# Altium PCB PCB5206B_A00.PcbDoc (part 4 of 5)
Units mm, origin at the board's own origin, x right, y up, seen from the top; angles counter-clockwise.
Board outline 115 x 60 mm, 6 copper layers (Top Layer, GND Layer 2, Signal Layer 3, Signal Layer 4, VCC Layer 5, Bottom Layer), stack 1.555 mm thick; 384 components, 267 nets, 1313 pads, 834 vias.
Unrouted connection lines stored in the file: 10.
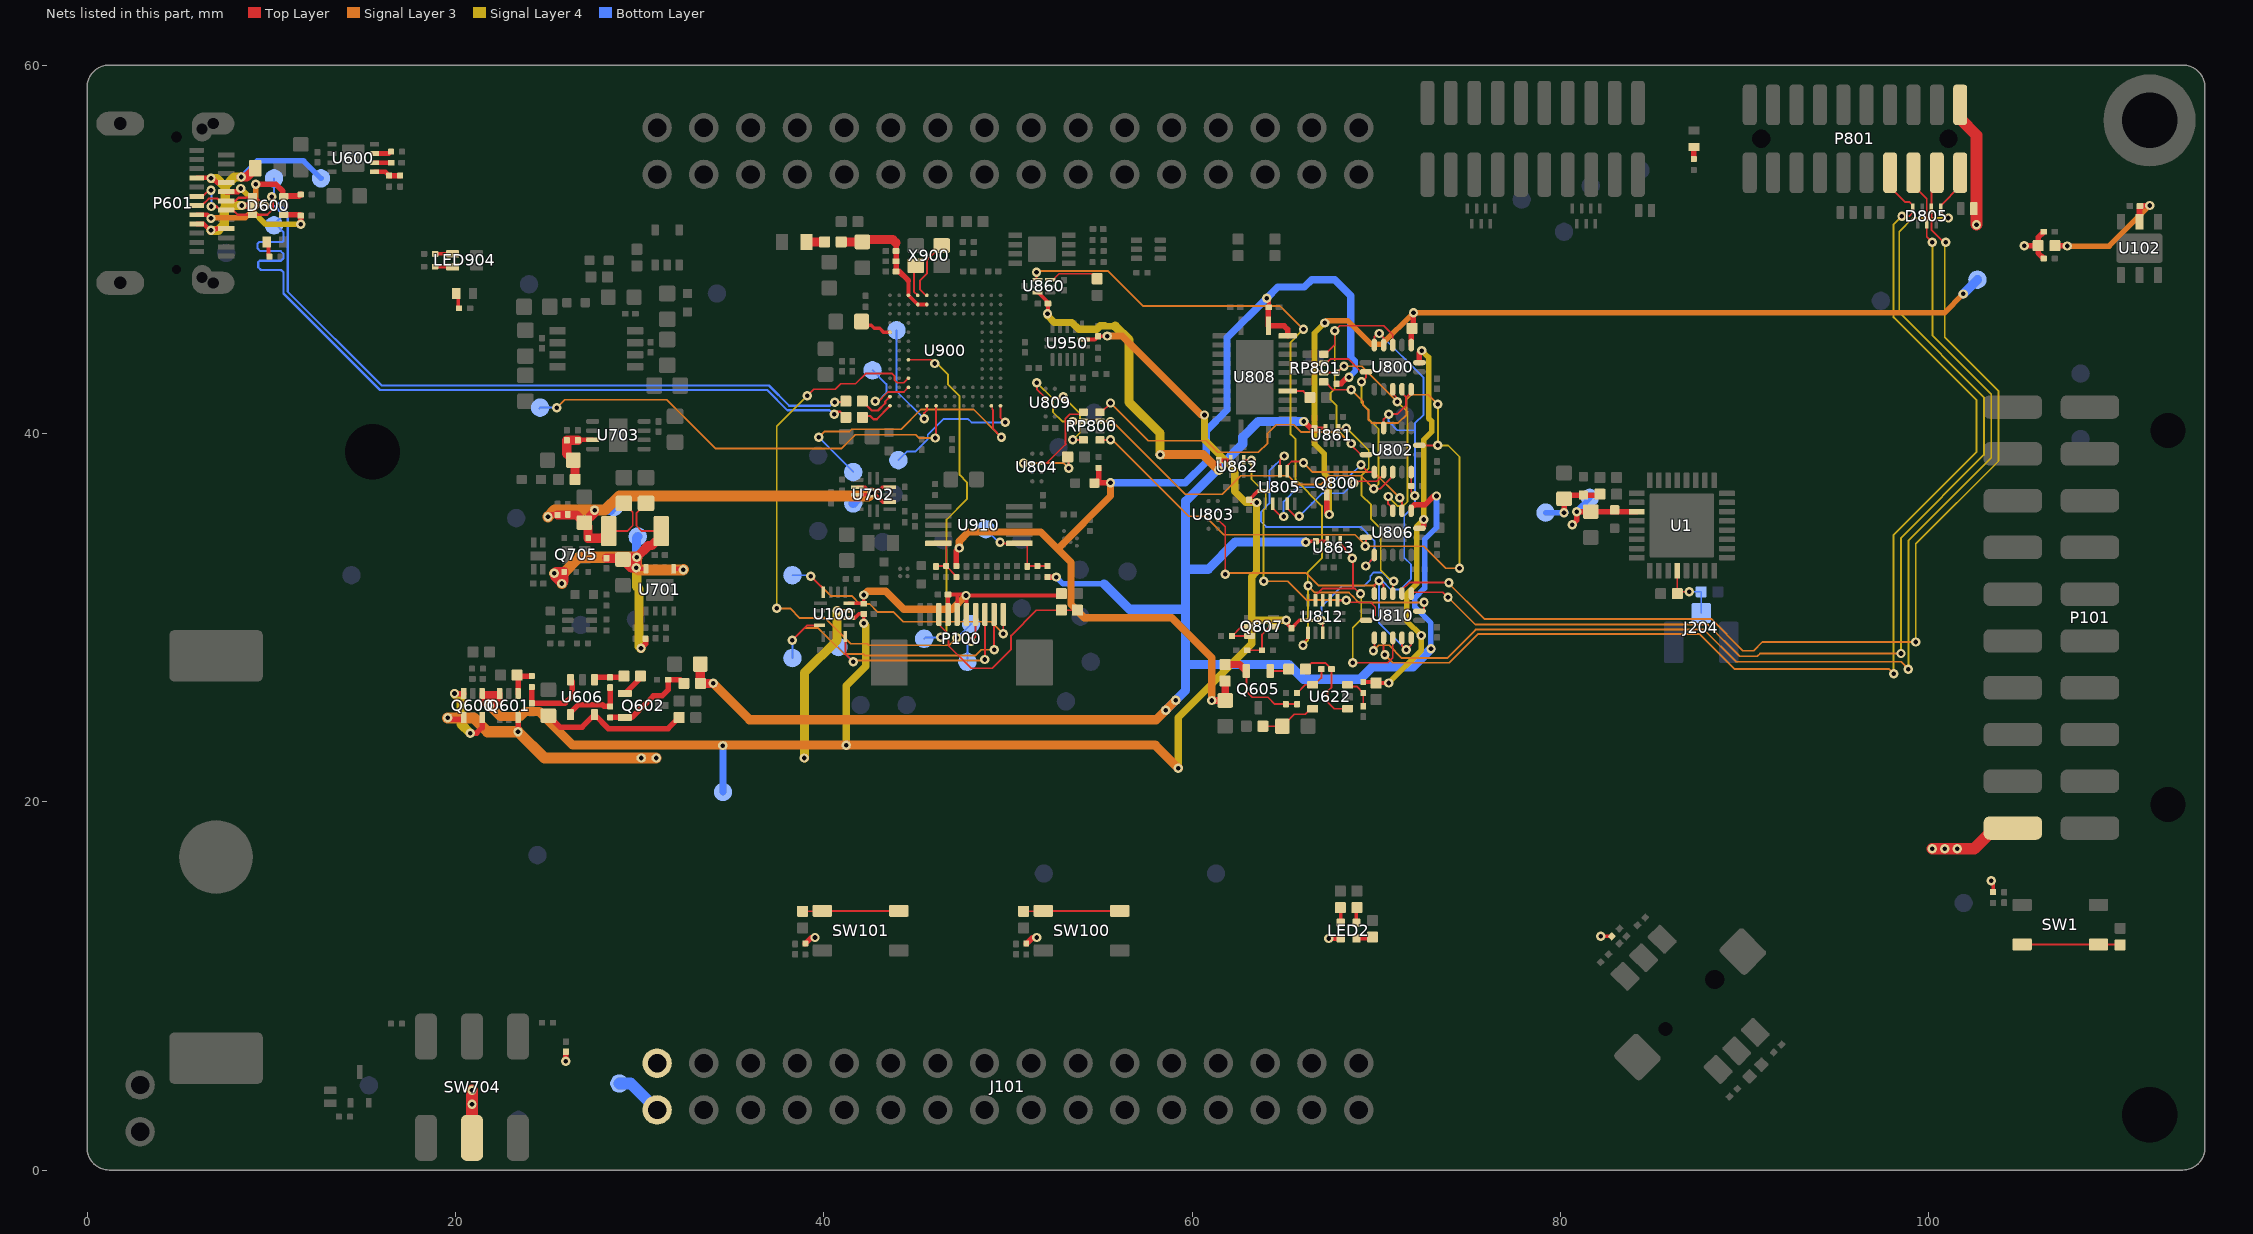
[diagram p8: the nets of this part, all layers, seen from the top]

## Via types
v1: diameter 0.508, hole 0.25, Top Layer to Bottom Layer, tented both sides, 834 vias

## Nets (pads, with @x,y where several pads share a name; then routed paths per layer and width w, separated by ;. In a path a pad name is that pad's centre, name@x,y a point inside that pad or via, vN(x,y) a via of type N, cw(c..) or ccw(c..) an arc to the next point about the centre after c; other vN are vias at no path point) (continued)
N16846723: R805.1 U808.17 | length 1.3
  Top Layer w0.1: U808.17@65.195,42.3 66.05,42.3 R805.1@66.4,41.95
N16846896: RP800.8 U809.C1 | length 3.9
  Top Layer w0.1: U809.C1@52.55,41.925 v1@52.975,41.925 ; v1(53.525,39.65) RP800.8@54.1,39.65
  Signal Layer 4 w0.1: v1(53,42) 53.925,41.075 53.925,40.05 v1(53.525,39.65)
N16846900: RP800.6 U809.C2 | length 4.8
  Top Layer w0.1: v1(51.575,42.75) 51.575,42.4 U809.C2@52.05,41.925 ; v1(53.525,40.65) RP800.6@54.1,40.65
  Signal Layer 4 w0.1: v1(51.575,42.75) 52.45,41.875 52.45,41.15 52.95,40.65 v1(53.525,40.65)
N16846924: RP800.5 U804.C1 | length 4.2
  Top Layer w0.1: U804.C1@51.825,38.4 52.125,38.4 53.125,39.4 53.125,40.8 53.132,40.807 53.132,40.813 53.362,41.043 53.993,41.043 RP800.5@54.1,41.15
N16847739: U805.10 U806.9 | length 13.9
  Top Layer w0.1: U805.10@64.775,37.955 64.775,38.55 v1(65,38.775) ; v1(69.425,32.8) 69.9,33.275 U806.9@69.9,33.4
  Bottom Layer w0.1: v1(65,38.775) 64.2,37.975 64.2,36.2 63.75,35.75 63.75,35.2 64.025,34.925 69.15,34.925 69.9,34.175 69.9,33.275 v1(69.425,32.8)
N16847741: U805.9 U806.3 | length 8.1
  Top Layer w0.1: U805.9@65.175,37.955 65.175,38.25 65.4,38.475 65.975,38.475 v1(66.05,38.4) ; v1(71.275,36.5) 71.4,36.375 U806.3@71.4,35.8
  Signal Layer 3 w0.1: v1(66.05,38.4) 66.55,37.9 69.881,37.9 71.275,36.506 v1(71.275,36.5)
N16847743: U802.10 U805.4 | length 6.7
  Top Layer w0.1: U805.4@65.175,36.185 65.175,35.925 65.6,35.5 v1(65.825,35.5) ; v1(68.775,37.3) 68.875,37.4 69.776,37.4 70.024,37.4 70.4,37.776 U802.10@70.4,37.9
  Bottom Layer w0.1: v1(65.825,35.5) 67.075,36.75 68.225,36.75 v1(68.775,37.3)
N16847749: U802.9 U805.2 | length 7.7
  Top Layer w0.1: U805.2@64.375,36.185 64.375,35.945 v1@64.795,35.525 ; v1@69,38.3 v1(69.175,38.3) 69.575,37.9 U802.9@69.9,37.9
  Bottom Layer w0.1: v1(64.975,35.491) 64.975,36.3 65.75,37.075 67.375,37.075 68,37.7 68.575,37.7 v1(69.175,38.3)
N16847975: R810.1 U804.C2 | length 3.7
  Top Layer w0.1: v1(50.85,38.388) 50.863,38.4 U804.C2@51.325,38.4 ; R810.1@53.25,38.725 53.3,38.675 v1(53.3,38.1)
  Signal Layer 3 w0.1: v1(50.85,38.388) 53.038,38.388 53.325,38.1 v1(53.3,38.1)
N16916520: U810.1 U812.1 U860.4 | length 43
  Top Layer w0.1: v1(51.553,48.752) 51.553,48.397 U860.4@51.6,48.35 ; v1(66.025,28.5) 66.025,28.625 66.3,28.9 U812.1@66.3,29.165 ; U810.1@72.35,30.35 72.375,30.375 72.55,30.375 72.6,30.425 v1(72.6,30.825)
  Signal Layer 3 w0.1: v1(51.553,48.752) 51.625,48.825 55.425,48.825 57.325,46.925 64.775,46.925 v1(66.05,45.65) ; v1(66.3,31.725) 66.668,31.357 68.524,31.357 68.807,31.074 68.807,31.062 69.037,30.832 69.049,30.832 69.056,30.825 v1(72.6,30.825)
  Signal Layer 4 w0.1: v1(66.025,28.5) 66.3,28.775 v1(66.3,31.725) 66.287,31.738 66.287,32.462 67.05,33.225 67.05,36.05 65.625,37.475 65.625,39.675 65.35,39.95 65.35,44.95 v1(66.05,45.65)
N16916530: U810.4 U812.3 U861.4 | length 17.4
  Top Layer w0.1: v1(67.025,29.85) 67.1,29.775 U812.3@67.1,29.165 ; U861.4@67.95,40.25 68.425,40.25 v1@68.45,40.275 ; U810.4@70.9,31.3 70.9,31.875 70.95,31.925 v1(70.95,31.975)
  Signal Layer 4 w0.1: v1(68.375,40.275) 68.4,40.275 69.6,39.075 69.6,38.1 69.2,37.7 69.2,36.65 69.725,36.125 69.725,35.35 70.25,34.825 70.25,32.575 70.85,31.975 v1(70.95,31.975)
  Bottom Layer w0.1: v1(67.025,29.85) 67.025,30.6 68.15,31.725 69.35,31.725 69.675,32.05 69.675,32.25 69.875,32.45 70.325,32.45 70.8,31.975 v1(70.95,31.975)
N16916558: U810.11 U812.11 U863.4 | length 13.2
  Top Layer w0.1: U812.11@66.7,30.935 66.7,31.2 67.075,31.575 68.743,31.575 ; U863.4@68.05,34.15 68.05,34.025 68.3,33.775 68.3,33.7 68.7,33.3 v1(68.7,33.225) 68.743,33.182 68.743,31.575 ; v1@68.723,27.55 70.625,27.55 70.9,27.825 U810.11@70.9,28.9 ; v1(69.15,31.3) 69.125,31.3 68.85,31.575 68.743,31.575
  Signal Layer 4 w0.1: v1(68.725,27.55) 68.725,29.439 69.193,29.907 69.193,31.218 69.15,31.261 v1(69.15,31.3)
N16916616: U810.8 U812.8 U862.4 | length 15.5
  Top Layer w0.1: U862.4@62.8,38.55 v1(63.225,38.55) ; U812.8@67.9,30.935 68.36,30.935 v1(68.375,30.95) 68.493,30.832 69.693,30.832 69.95,30.575 69.95,30.125 69.675,29.85 U810.8@69.45,29.85
  Signal Layer 3 w0.1: v1(63.9,31.975) 65.2,31.975 66.225,30.95 v1(68.375,30.95)
  Signal Layer 4 w0.1: v1(63.225,38.55) 63.225,37.525 64,36.75 64,35.95 63.875,35.825 v1@63.875,31.975
N16917071: R882.1 U860.3 | length 2.8
  Top Layer w0.1: U860.3@52.3,48.35 52.45,48.35 52.775,48.675 54.575,48.675 R882.1@54.85,48.4
N16922979: R601.1 R602.2 U600.5 | length 1.5
  Top Layer w0.25: U600.5@15.6,54.2 16.2,54.2 R601.1@16.4,54
  Top Layer w0.3: R601.1@16.4,54 R602.2@17,54
N16923003: R600.1 U600.7 | length 0.9
  Top Layer w0.25: U600.7@15.6,55.2 16.4,55.2 R600.1@16.5,55.3
N16923019: C602.1 U600.6 | length 0.9
  Top Layer w0.25: U600.6@15.6,54.7 C602.1@16.525,54.7
N16923678: C620.1 R682.2 U606.4 | length 3.5
  Top Layer w0.3: U606.4@26.25,24.725 26.25,24.85 26.675,25.275 27.975,25.275 28.075,25.175 R682.2@28.4,25.175 C620.1@28.4,26.2
N16923728: Q601.4 R628.1 R672.2 | length 1.8
  Top Layer w0.3: R628.1@23.35,26.875 R628.1@23.4,26.825 ; Q601.4@23.4,25.875 R628.1@23.4,26.825 ; R672.2@24.15,26.825 R628.1@23.4,26.825
N16923751: C654.1 R689.2 U622.4 | length 2.1
  Top Layer w0.1: R689.2@65.7,25.9 66.15,26.35 U622.4@66.55,26.35 66.65,26.35 67.025,26.725 C654.1@67.025,27.2
N16923761: Q605.1 R686.2 | length 1
  Top Layer w0.1: Q605.1@64.25,27.1 65.15,27.1 R686.2@65.25,27.2
N16923771: C653.1 R629.1 U622.3 | length 1.8
  Top Layer w0.1: U622.3@68.45,26.35 68.539,26.261 68.939,26.261 R629.1@69.3,25.9 C653.1@69.3,25.175
N16923785: Q605.2 R687.1 R688.1 R689.1 | length 5.4
  Top Layer w0.1: Q605.2@62.95,27.1 62.95,26 63.275,25.675 64.125,25.675 64.5,25.3 R688.1@65.1,25.3 R689.1@65.7,25.3
  Top Layer w0.4: R687.1@61.8,27.45 62.6,27.45 Q605.2@62.95,27.1
N16923803: C654.2 R686.1 U622.1 | length 4.8
  Top Layer w0.1: R686.1@66.15,27.2 66.475,27.525 67.25,27.525 C654.2@67.575,27.2 67.575,26.225 67.35,26 67.35,25.425 67.725,25.05 U622.1@68.45,25.05
N16923899: C652.1 R690.1 U622.5 | length 3.1
  Top Layer w0.1: R690.1@63.85,24.1 C652.1@64.9,24.1 65.55,24.75 66.15,24.75 66.45,25.05 U622.5@66.55,25.05
N16923917: C660.1 R681.1 U606.5 | length 8.2
  Top Layer w0.3: C660.1@25.05,24.675 25.675,24.05 26.875,24.05 U606.5@27.55,24.725 28.3,23.975 31.55,23.975 R681.1@32.15,24.575
N16923949: Q602.1 R679.2 | length 1.3
  Top Layer w0.3: Q602.1@29.2,25.875 30.05,26.725 R679.2@30.05,26.825
N16923963: C621.1 R672.1 U606.3 | length 4.2
  Top Layer w0.3: R672.1@24.15,26.225 C621.1@24.15,25.35 25.95,25.35 26.35,25.75 26.35,26.525 U606.3@26.25,26.625
N16923985: Q602.2 R674.1 R675.1 R682.1 | length 5.3
  Top Layer w0.3: R682.1@28.4,24.575 Q602.2@29.2,24.575 29.575,24.575 30.75,25.75 31.225,25.75 31.55,26.075 R674.1@31.55,26.625 32.2,26.625 R675.1@32.4,26.425
N16924018: C620.2 R679.1 U606.1 | length 1.7
  Top Layer w0.3: U606.1@27.55,26.625 27.675,26.75 C620.2@28.4,26.75 29.075,26.75 R679.1@29.15,26.825
N16924927: Q600.3 Q600.6 | length 4.3
  Top Layer w0.3: v1(19.95,25.875) Q600.6@20.45,25.875 ; v1(20.8,23.725) 21.15,23.725 21.45,24.025 Q600.3@21.45,24.575
  Signal Layer 4 w0.5: v1(19.95,25.875) 20.3,25.525 20.3,24.225 v1(20.8,23.725)
N16934878: C900.1 U900.J13 | length 1.7
  Top Layer w0.2: C900.1@42.05,45.975 42.15,45.875 42.575,45.875 42.743,45.707 43.039,45.707 43.246,45.5 U900.J13@43.6,45.5
N16934900: C903.1 C904.1 C905.1 C906.1 R130.2 U900.M9 U900.M10 U900.N11 | length 7.5
  Top Layer w0.2: 44.6,48.3 U900.N11@44.6,47.5 U900.M10@45.1,47 U900.M9@45.6,47
  Top Layer w0.3: 43.925,50.35 C906.1@43.925,49.9 C905.1@43.925,49.35 C904.1@43.925,48.8 44.1,48.8 44.6,48.3
  Top Layer w0.5: R130.2@40.95,50.4 C903.1@42.1,50.4 42.225,50.525 43.75,50.525 43.925,50.35
N16936696: U900.N10 X900.1 | length 1.7
  Top Layer w0.1: X900.1@45,49.1 44.9,49 44.9,47.7 U900.N10@45.1,47.5
N16936699: U900.N9 X900.3 | length 3.4
  Top Layer w0.1: U900.N9@45.6,47.5 45.55,47.5 45.225,47.825 45.225,48.3 45.6,48.675 45.6,49.4 X900.3@46.4,50.2
N16939106: TPJ909.1 U900.C11 | length 4.5
  Top Layer w0.1: v1(42.8,41.75) 42.873,41.677 42.902,41.677 43.475,42.25 44.35,42.25 U900.C11@44.6,42.5
  Bottom Layer w0.1: TPJ909.1@42.651,43.427 43.4,42.679 43.4,42.2 42.95,41.75 v1(42.8,41.75) v1@42.8,41.7
N16939109: TPJ910.1 U900.D11 | length 30.5
  Top Layer w0.1: v1(39.1,42.05) 39.45,42.4 40.625,42.4 40.925,42.7 41.725,42.7 42.275,43.25 43.714,43.25 43.85,43.114 43.85,42.886 43.986,42.75 44.35,42.75 U900.D11@44.6,43
  Signal Layer 3 w0.1: v1(37.45,30.5) 38.175,30.5 38.7,29.975 40.075,29.975 41.475,28.575 42.375,28.575 42.45,28.5 46.825,28.5 v1(47.225,28.9)
  Signal Layer 4 w0.1: v1(37.45,30.5) 37.45,40.4 v1(39.1,42.05)
  Bottom Layer w0.1: v1(47.225,28.9) 47.253,28.9 TPJ910.1@48.003,29.65
N16939489: TPJ911.1 U900.F11 | length 18.7
  Top Layer w0.1: U900.F11@44.6,44 45.825,44 v1(46.025,43.8)
  Signal Layer 4 w0.1: v1(46.025,43.8) 46.125,43.8 46.75,43.175 46.75,42.65 47.375,42.025 47.375,37.75 47.775,37.35 47.775,36.425 46.675,35.325 46.675,29.25 v1(46.35,28.925)
  Bottom Layer w0.1: TPJ911.1@45.453,28.85 45.528,28.925 v1(46.35,28.925)
N16939638: TPJ900.1 U900.A2 | length 15.8
  Top Layer w0.1: U900.A2@49.1,41.5 49.15,41.45 49.15,41.314 49.2,41.264 49.2,40.25 v1(49.65,39.8)
  Signal Layer 3 w0.1: v1(39.725,39.8) 40.025,40.1 41.4,40.1 41.525,40.225 44.2,40.225 45.275,41.3 48.15,41.3 v1(49.65,39.8)
  Bottom Layer w0.1: v1(39.725,39.8) 41.602,37.923 TPJ900.1@41.602,37.9
N16939640: TPJ901.1 U900.A1 | length 7.9
  Top Layer w0.1: U900.A1@49.6,41.5 49.6,40.85 v1(49.85,40.6)
  Bottom Layer w0.1: TPJ901.1@44.053,38.55 44.528,39.025 45,39.025 45.65,39.675 45.65,39.925 46.5,40.775 47.85,40.775 48.025,40.6 v1(49.85,40.6)
N16940103: TPJ908.1 U900.A9 | length 6.2
  Top Layer w0.1: v1(45.45,40.8) 45.45,41.1 45.6,41.25 U900.A9@45.6,41.5
  Bottom Layer w0.1: TPJ908.1@43.952,45.601 43.952,42.298 v1(45.45,40.8)
N16942491: R902.2 U900.B13 | length 2.1
  Top Layer w0.12: R902.2@42.1,41.75 42.6,41.25 42.95,41.25 43.34,41.64 43.34,41.74 U900.B13@43.6,42
N16942503: R904.2 U900.A13 | length 1.9
  Top Layer w0.12: R904.2@42.1,40.875 42.175,40.95 42.525,40.95 42.7,40.775 42.875,40.775 U900.A13@43.6,41.5
N16943456: TPJ902.1 U900.A8 | length 24.9
  Top Layer w0.1: v1(46.05,39.75) 46.1,39.8 U900.A8@46.1,41.5
  Signal Layer 3 w0.1: v1(25.5,41.4) 25.925,41.825 31.484,41.825 34.134,39.175 40.95,39.175 41.7,39.925 45,39.925 45.175,39.75 v1(46.05,39.75)
  Bottom Layer w0.1: TPJ902.1@24.551,41.351 TPJ902.1@24.6,41.4 v1(25.5,41.4)
N16944010: LED903.2 R912.2 | length 0.9
  Top Layer w0.2: LED903.2@20.05,47.6 20.15,47.5 20.15,46.85 R912.2@20.2,46.8
N16966205: LED904.2 R920.2 | length 0.9
  Top Layer w0.2: R920.2@18.9,49.75 LED904.2@19.85,49.75
N16966207: LED904.1 R919.2 | length 0.9
  Top Layer w0.2: R919.2@18.9,49.05 LED904.1@19.85,49.05
N16966211: LED901.1 R903.2 | length 0.9
  Top Layer w0.2: LED901.1@9.75,50.4 9.85,50.3 9.85,49.65 R903.2@9.9,49.6
N16966215: LED900.1 R900.2 | length 0.7
  Top Layer w0.3: R900.2@87.25,54.9 LED900.1@87.25,55.55
N16996446: Q807.5 Q807.6 R838.1 | length 2.1
  Top Layer w0.1: Q807.6@63.125,29 R838.1@62.175,29 62.675,29.5 Q807.5@63.125,29.5
N16997087: Q807.2 R839.2 R841.2 | length 2.5
  Top Layer w0.1: R841.2@63,28.225 R839.2@63.8,28.225 63.8,29.075 64.225,29.5 Q807.2@64.425,29.5
N17012885: L900.2 R130.1 | length 1
  Top Layer w0.5: L900.2@39.065,50.4 R130.1@40.05,50.4
N17207915: LED2.4 R135.1 | length 0.9
  Top Layer w0.2: LED2.4@68.925,12.575 69.725,12.575 R135.1@69.8,12.65
N17207930: LED2.3 R136.1 | length 0.9
  Top Layer w0.2: R136.1@68.875,14.175 R136.1@68.95,14.25 ; LED2.3@68.925,13.425 R136.1@68.925,14.175
N17207934: LED2.2 R137.1 | length 0.8
  Top Layer w0.2: R137.1@68.025,14.225 R137.1@68.05,14.25 ; LED2.2@68.075,13.425 R137.1@68.075,14.225
N17208223: P100.3 R145.1 R146.2 | length 11.2
  Top Layer w0.1: P100.3@46.25,30.175 46.25,29.625 46.775,29.1 46.775,28.475 48,27.25 49.15,27.25 50.175,28.275 50.175,29.025 51.55,30.4 R145.1@52.9,30.4 R146.2@53.775,30.4
N17208307: P100.10 TP150.1 U100.16 | length 15
  Top Layer w0.1: v1(39.3,32.25) 39.975,31.575 U100.16@39.975,31.375 ; v1(49.75,29.125) P100.10@49.75,30.175
  Signal Layer 3 w0.1: v1(39.3,32.25) 40.375,31.175 41.525,31.175 41.962,30.738 42.487,30.738 42.925,30.3 43.8,30.3 44.325,29.775 49.1,29.775 v1(49.75,29.125)
  Bottom Layer w0.1: TP150.1@38.3,32.3 39.25,32.3 v1(39.3,32.25)
N17208309: P100.9 TP151.1 U100.4 | length 16.7
  Top Layer w0.1: v1(38.3,28.775) 39.1,29.575 U100.4@39.775,29.575 ; v1(49.25,28.25) P100.9@49.25,30.175
  Signal Layer 3 w0.1: v1(38.3,28.775) 38.95,29.425 39.7,29.425 41.1,28.025 42.15,28.025 42.225,27.95 48.25,27.95 48.55,28.25 v1(49.25,28.25)
  Bottom Layer w0.1: TP151.1@38.3,27.8 v1(38.3,28.775)
N17208311: P100.8 TP152.1 U100.8 | length 12.3
  Top Layer w0.1: U100.8@41.175,28.975 41.175,28.025 v1(41.6,27.6) ; v1(48.75,27.725) P100.8@48.75,30.175
  Signal Layer 3 w0.1: v1(41.6,27.6) 41.675,27.675 v1@48.75,27.675
  Bottom Layer w0.1: TP152.1@40.8,28.4 v1(41.6,27.6)
N17208347: P100.7 TP153.1 | length 2.8
  Top Layer w0.1: v1(48,28.7) 48.25,28.95 P100.7@48.25,30.175
  Bottom Layer w0.1: TP153.1@47.8,27.6 47.8,28.5 v1(48,28.7)
N17209732: R104.1 SW100.1 SW100.2 | length 5.2
  Top Layer w0.1: R104.1@50.85,14.05 51.9,14.05 SW100.1@51.925,14.075 SW100.2@56.075,14.075
N17209791: R105.1 SW101.1 SW101.2 | length 5.2
  Top Layer w0.1: R105.1@38.85,14.05 39.9,14.05 SW101.1@39.925,14.075 SW101.2@44.075,14.075
N17211545: C110.1 R150.1 U102.5 | length 7.3
  Top Layer w0.3: R150.1@106.85,50.2 107.51,50.2 v1(107.535,50.175) ; U102.5@111.45,51.5 111.45,52.175 C110.1@111.525,52.25 ; C110.1@111.525,52.375 v1(112,52.375)
  Signal Layer 3 w0.3: v1(107.535,50.175) 109.8,50.175 v1(112,52.375)
N17247543: R7.2 SW1.3 SW1.4 | length 5.3
  Top Layer w0.1: SW1.3@105.075,12.25 SW1.4@109.225,12.25 110.375,12.25 R7.2@110.4,12.225
SI_HEADER_ENABLE: R807.2 U800.5 U800.6 U800.12 U800.13 U802.5 U802.13 U803.C2 U810.5 U810.6 U810.12 U810.13 | length 44.8
  Top Layer w0.1: U803.C2@61.4,35.325 61.8,34.925 v1(61.8,32.35) ; U810.6@69.9,31.3 69.9,31.75 v1(70.15,32) 70.4,31.75 U810.5@70.4,31.3 ; U800.6@69.9,44.8 69.9,45.25 70.075,45.425 v1(70.175,45.425) 70.4,45.2 U800.5@70.4,44.8 ; U802.5@70.4,40.3 70.4,40.775 v1(70.675,41.05) 71.15,41.05 71.625,41.525 71.625,41.975 ; U810.12@71.4,28.9 71.4,28.475 v1(71.625,28.25) 71.9,28.525 U810.13@71.9,28.9 ; U800.12@71.4,42.4 71.4,42.2 71.625,41.975 ; U802.13@71.9,37.9 R807.2@71.9,37.15 71.9,36.825 v1(72.1,36.625) ; U800.13@71.9,42.4 71.9,42.25 71.625,41.975
  Signal Layer 3 w0.1: v1@61.85,32.425 66.175,32.425 66.85,31.75 69.9,31.75 v1(70.15,32)
  Bottom Layer w0.1: v1(70.175,45.425) 72.575,43.025 72.575,41.025 72.1,40.55 72.1,40.175 ; v1(70.675,41.05) 70.675,40.65 71.15,40.175 72.1,40.175 ; v1(71.625,28.25) 70.15,29.725 v1(70.15,32) 70.325,32 70.8,31.525 71.3,31.525 71.893,32.118 71.893,32.882 71.525,33.25 71.525,35.525 72.1,36.1 v1(72.1,36.625) 72.1,40.175
SI_VCOM_CTS: D805.4 P801.8 U810.10 | length 62.6
  Top Layer w0.1: U810.10@70.4,28.9 70.4,28.05 v1(70.475,27.975) ; P801.8@97.905,54.158 97.905,53.37 98.7,52.575 98.95,52.575 99.15,52.375 D805.4@99.15,52.215 99.15,52 98.95,51.8 v1(98.55,51.8)
  Signal Layer 3 w0.1: v1(70.475,27.975) 70.9,27.55 73.975,27.55 75.525,29.1 87.575,29.1 89.475,27.2 97.85,27.2 v1(98.1,26.95)
  Signal Layer 4 w0.1: v1(98.1,26.95) 98.1,34.5 102.6,39 102.6,41.803 98.1,46.303 98.1,51.35 v1(98.55,51.8)
SI_VCOM_RTS: D805.6 P801.6 U810.9 | length 62.3
  Top Layer w0.1: v1(69.85,28.2) 69.9,28.25 U810.9@69.9,28.9 ; P801.6@99.175,54.158 99.175,53.475 99.9,52.75 D805.6@99.9,51.385 99.9,50.675 v1(100.2,50.375)
  Signal Layer 3 w0.1: v1(69.85,28.2) 70.15,28.5 70.7,28.5 71.4,27.8 73.85,27.8 75.4,29.35 87.8,29.35 89.55,27.6 98.5,27.6 v1(98.9,27.2)
  Signal Layer 4 w0.1: v1(98.9,27.2) 98.9,34.169 103.4,38.669 103.4,42.134 100.2,45.334 v1(100.2,50.375)
SI_VCOM_RXD: D805.1 P801.2 U810.2 | length 61
  Top Layer w0.1: U810.2@71.9,31.3 71.9,31.375 73.625,31.375 v1(73.9,31.1) ; v1(101.075,51.7) 101,51.7 100.65,52.05 D805.1@100.65,52.215 100.65,52.375 101.715,53.44 P801.2@101.715,54.158
  Signal Layer 3 w0.1: v1(73.9,31.1) 75.375,29.625 88.012,29.625 89.737,27.9 90.7,27.9 90.85,28.05 v1(98.5,28.05)
  Signal Layer 4 w0.1: v1(98.5,28.05) 98.5,34.334 103,38.834 103,41.969 98.4,46.569 98.4,50.95 99.15,51.7 v1(101.075,51.7)
SI_VCOM_TXD: D805.2 P801.4 U810.3 | length 59.1
  Top Layer w0.1: U810.3@71.4,31.3 71.4,31.5 71.8,31.9 v1(73.95,31.9) ; P801.4@100.445,54.158 100.15,53.863 D805.2@100.15,52.215 100.15,51.05 100.825,50.375 v1(100.925,50.375)
  Signal Layer 3 w0.1: v1@73.9,31.9 75.875,29.925 88.188,29.925 89.913,28.2 90.5,28.2 90.975,28.675 v1(99.3,28.675)
  Signal Layer 4 w0.1: v1(99.3,28.675) 99.3,34.003 103.8,38.503 103.8,42.3 100.875,45.225 v1@100.875,50.375
TCK_SWCLK: RP800.3 RP801.3 U800.8 U802.11 | length 29.5
  Top Layer w0.1: RP800.3@55,40.65 v1(55.575,40.65) ; RP801.3@67.15,43.8 67.289,43.8 67.539,44.05 68.475,44.05 69.175,43.35 U800.8@69.45,43.35 69.45,43.05 v1@69.203,42.803 ; v1(69.875,37) 70.224,37 70.9,37.676 U802.11@70.9,37.9
  Signal Layer 3 w0.1: v1@55.575,40.75 59.625,36.7 61.65,36.7 62.65,37.7 65.225,37.7 65.7,37.225 67,37.225 67.475,37.7 69.175,37.7 v1(69.875,37)
  Signal Layer 4 w0.1: 69.203,42.35 69.203,41.672 ; v1(69.203,42.802) 69.203,41.672 ; v1(69.875,37) 70.125,37.25 70.125,40.25 69.575,40.8 69.575,41.3 69.203,41.672
TDI: RP800.1 RP801.1 U802.1 U806.8 | length 42.4
  Top Layer w0.1: RP800.1@55,39.65 v1(55.575,39.65) ; RP801.1@67.15,42.8 67.227,42.8 67.652,42.375 v1(68.65,42.375) ; v1@69.45,33.975 U806.8@69.45,34.35 ; U802.1@72.35,39.35 v1(73.35,39.35)
  Signal Layer 3 w0.1: v1@55.575,39.75 59.825,35.5 60.725,35.5 61.725,34.5 68.85,34.5 69.4,33.95 v1(69.4,33.875) 72.575,33.875 73.775,32.675 v1(74.525,32.675) ; v1(68.65,42.375) 69.275,41.75 69.275,41.55 69.575,41.25 69.575,40.75 69.75,40.575 71.2,40.575 71.65,41.025 71.65,41.85 71.9,42.1 72.825,42.1 v1(73.35,41.575)
  Signal Layer 4 w0.1: v1(73.35,41.575) v1(73.35,39.35) 73.9,39.35 74.525,38.725 74.525,35.65 v1(74.525,32.675)
TDO_SWO: R801.1 RP801.2 U800.11 U806.4 | length 13.6
  Top Layer w0.1: RP801.2@67.15,43.3 R801.1@67.85,43.3 68.175,43.625 68.225,43.625 v1(68.25,43.65) ; v1(70.65,36.575) 70.65,36.174 70.9,35.924 U806.4@70.9,35.8 ; U800.11@70.9,42.4 70.9,42.175 71.15,41.925 v1(71.15,41.725)
  Signal Layer 3 w0.1: v1(68.25,43.65) 69.225,43.65 v1(71.15,41.725)
  Signal Layer 4 w0.1: v1(70.65,36.575) 70.65,36.569 71.169,36.05 71.45,36.05 71.7,36.3 71.7,41.175 v1(71.15,41.725)
TMS_SWDIO: RP800.4 RP801.4 U800.4 U802.8 | length 29.8
  Top Layer w0.1: RP800.4@55,41.15 55.075,41.15 v1(55.575,41.65) ; RP801.4@67.15,44.3 67.225,44.3 67.75,44.825 v1(67.75,45.575) 68.025,45.85 70.4,45.85 70.9,45.35 U800.4@70.9,44.8 ; v1(68.65,39.45) 68.575,39.45 69.175,38.85 U802.8@69.45,38.85
  Signal Layer 3 w0.1: v1(55.575,41.65) 57.625,39.6 60.775,39.6 61.4,38.975 63.606,38.975 64.1,39.469 64.1,40 64.575,40.475 65.525,40.475 65.925,40.075 67.975,40.075 68.6,39.45 v1(68.65,39.45)
  Signal Layer 4 w0.1: v1(67.75,45.575) 67.75,42.425 67.525,42.2 67.525,41.825 67.85,41.5 67.85,40.225 68.625,39.45 v1(68.65,39.45)
UFL_ADC_IN: J204.1 R220.2 R305.2 U1.12 | length 3.6
  Top Layer w0.1: U1.12@86.35,32.55 86.35,31.4 v1(87,31.4)
  Bottom Layer w0.1: v1(87,31.4) R220.2@87.65,31.4 J204.1@87.65,30.25
USB_DM: D600.6 P601.A7 P601.B7 R902.1 TPJ612.1 | length 45.6
  Top Layer w0.12: P601.B7@5.95,52.875 6.275,52.875 6.6,53.2 v1(6.725,53.2) ; v1@6.75,52.35 7,52.35 7.225,52.125 P601.A7@7.55,52.125 7.925,52.125 8.175,51.875 D600.6@8.975,51.875 9.778,51.875 10.075,52.172 10.075,52.8 v1(10.025,52.85) ; v1(40.6,41.7) 41.15,41.7 R902.1@41.2,41.75
  Bottom Layer w0.12: v1@6.725,53.15 6.75,53.125 v1@6.75,52.35 ; TPJ612.1@10.15,53.85 10.15,52.975 v1(10.025,52.85) 10.9,51.975 10.9,47.7 16,42.6 37.025,42.6 38.125,41.5 40.325,41.5 40.525,41.7 v1(40.6,41.7)
  other v1: 6.75,52.325
USB_DP: D600.4 P601.A6 P601.B6 R904.1 TPJ611.1 | length 48.6
  Top Layer w0.12: P601.B6@5.95,52.375 6.225,52.375 6.6,52.75 7.075,52.75 7.2,52.625 P601.A6@7.55,52.625 8.05,52.625 8.225,52.8 8.775,52.8 8.85,52.875 D600.4@8.975,52.875 9.138,52.875 9.65,52.363 v1(9.65,52.35) ; v1(40.575,41.05) 40.575,41.173 40.577,41.175 40.9,41.175 R904.1@41.2,40.875
  Bottom Layer w0.12: v1(9.65,52.35) 10.175,52.35 10.55,51.975 10.55,51.762 10.15,51.362 TPJ611.1@10.15,51.3 10.291,51.3 10.66,50.931 10.66,50.47 10.59,50.4 9.347,50.4 9.25,50.303 9.25,50.05 9.4,49.9 10.516,49.9 10.66,49.756 10.66,49.51 10.525,49.375 9.372,49.375 9.297,49.3 9.297,49.02 9.442,48.875 10.53,48.875 10.66,48.745 10.66,47.601 15.901,42.36 36.926,42.36 38.026,41.26 40.315,41.26 40.525,41.05 v1(40.575,41.05)
USBC_CC1: D600.1 P601.A5 R621.2 | length 6.7
  Top Layer w0.3: P601.A5@7.55,53.125 8.175,53.125 v1(8.35,53.3) ; D600.1@10.675,51.875 11.55,51.875 R621.2@11.6,51.825 v1(11.6,51.35)
  Signal Layer 4 w0.3: v1(8.35,53.3) 8.975,52.675 8.975,52.075 9.7,51.35 v1(11.6,51.35)
USBC_CC2: D600.3 P601.B5 R620.2 | length 7.7
  Top Layer w0.25: P601.B5@5.95,51.875 6.525,51.875 6.7,51.7 v1@6.725,51.7
  Top Layer w0.3: v1(9.15,53.525) 10.25,53.525 10.625,53.15 10.625,52.925 D600.3@10.675,52.875 10.693,52.893 11.5,52.893 11.5,52.875 R620.2@11.6,52.975
  Signal Layer 3 w0.3: v1@6.725,51.7 8.575,51.7 9.15,52.275 v1(9.15,53.525)
  other v1: 6.725,51.675
USBC_VBUS: D600.5 L600.1 P601.A4 P601.A9 P601.B4 P601.B9 TPJ613.1 | length 16.1
  Top Layer w0.25: P601.B4@5.95,51.375 6.323,51.375 6.725,50.973 v1(6.725,51.025) 6.725,51.05 6.925,51.05 7,51.125 P601.A9@7.55,51.125 ; P601.B9@5.95,53.875 6.7,53.875 v1(6.725,53.85) 6.825,53.85 7.05,53.625 P601.A4@7.55,53.625
  Top Layer w0.35: v1(8.4,52.375) D600.5@8.975,52.375
  Top Layer w0.5: v1(8.375,53.925) 8.66,53.925 L600.1@9.135,54.4
  Signal Layer 4 w0.5: v1(6.725,51.025) 7.125,51.025 7.45,51.35 7.45,52.2 7.625,52.375 ; v1(6.725,53.85) 7.025,53.85 7.5,53.375 ; v1(8.375,53.925) 8,53.925 7.5,53.425 7.5,53.375 ; v1(8.4,52.375) 7.625,52.375 ; 7.5,53.375 7.5,52.5 7.625,52.375
  Bottom Layer w0.3: v1(8.375,53.925) 9.25,54.8 11.75,54.8 TPJ613.1@12.7,53.85
V_SW: C104.1 C800.1 C828.1 C950.1 Q600.4 Q601.6 TPJ608.1 U100.10 U805.14 U812.14 U950.14 | length 90.6
  Top Layer w0.2: U100.10@41.375,29.975 41.675,29.975 41.9,30.2 C104.1@42.175,30.2 v1(42.175,29.7) ; U950.14@54.11,45.1 54.725,45.1 C950.1@54.9,45.275 v1@55.4,45.275 ; v1(63.521,36.25) 63.55,36.25 63.525,36.275 63.225,36.275 C800.1@63.1,36.4 63.57,36.87 U805.14@63.89,36.87 ; v1(65.125,29.85) 65.125,29.7 C828.1@65.4,29.425 65.825,29.85 U812.14@66.215,29.85
  Top Layer w0.3: 21.45,25.475 22.282,25.475 22.341,25.416 ; 21.45,25.475 Q600.4@21.45,25.625 ; 21.45,25.475 21.7,25.225 v1(21.85,25.225) 22.15,25.225 22.341,25.416 ; Q600.4@21.45,25.625 Q601.6@22.4,25.625 ; Q600.4@21.45,25.625 Q600.4@21.45,25.875 Q601.6@22.4,25.875 Q601.6@22.4,25.625 ; 22.341,25.416 22.4,25.475 Q601.6@22.4,25.625
  Signal Layer 3 w0.4: v1(55.4,45.287) 56.213,45.287 60.5,41 v1(60.675,41)
  Signal Layer 3 w0.5: v1(21.85,25.225) 22.45,24.625 23.525,24.625 23.8,24.9 24.55,24.9 26.375,23.075 v1(41.225,23.075) 58,23.075 v1(59.25,21.825)
  Signal Layer 4 w0.4: v1(41.225,23.075) 41.225,26.3 42.275,27.35 42.275,29.6 v1(42.175,29.7) ; v1(59.25,21.825) 59.25,24.575 63.25,28.575 63.25,29.85 ; v1(60.675,41) 60.675,39.65 62.325,38 62.325,36.85 62.925,36.25 v1(63.521,36.25) 63.5,36.229 63.5,32.475 63.25,32.225 63.25,29.85 ; v1(65.125,29.85) 63.25,29.85
  Bottom Layer w0.4: v1(34.525,23.05) 34.528,23.047 TPJ608.1@34.528,20.527
VCOM_CTS: U812.9
VCOM_RTS: U812.10
VCS: C710.1 C714.1 C728.1 R717.2 U703.7 | length 3.7
  Top Layer w0.25: C710.1@26.675,39.65 U703.7@27.45,39.65
  Top Layer w0.3: C710.1@26.65,39.625 C710.1@26.675,39.65
  Top Layer w0.5: R717.2@26.5,37.5 26.5,38.45 C714.1@26.4,38.55 26.05,38.9 C728.1@26.05,39.625 C710.1@26.65,39.625
VDISP: C143.1 C144.1 P100.4 P100.5 P100.6 R145.2 U100.12 | length 17
  Top Layer w0.2: U100.12@41.375,30.775 42.15,30.775 C144.1@42.175,30.75 v1(42.175,31.225) ; P100.4@46.75,30.175 C143.1@46.75,31.25 47.25,31.25 ; P100.5@47.25,30.175 47.25,31.25 ; P100.6@47.75,30.175 47.75,31.175 v1(47.725,31.2) ; R145.2@52.9,31.3 52.8,31.2 v1(47.725,31.2) ; 47.25,31.25 47.675,31.25 v1(47.725,31.2)
  Signal Layer 3 w0.4: v1(42.175,31.225) 42.375,31.425 43.375,31.425 44.35,30.45 46.975,30.45 v1(47.725,31.2)
VMCU: C1.1 C2.1 C706.1 D808.1 J101.1 J101.2 LED2.1 P101.2 P801.1 Q600.1 Q601.3 R9.1 R100.2 R101.2 R108.1 R109.1 R111.2 R150.2 SW704.5 TP157.1 TP703.1 U1.3 U100.11 | length 51.3
  Top Layer w0.2: v1(40.725,30.375) U100.11@41.375,30.375 ; v1(82.2,12.7) 82.212,12.688 R111.2@82.788,12.688 ; v1(103.4,15.7) 103.5,15.6 R9.1@103.5,15.1
  Top Layer w0.3: v1(19.577,24.551) 19.577,24.548 19.65,24.475 20.35,24.475 Q600.1@20.45,24.575 ; v1(23.4,23.8) Q601.3@23.4,24.575 ; v1(26,5.9) 26,5.925 C706.1@26,6.425 ; R101.2@39,12.3 39.325,12.625 v1(39.525,12.625) ; R100.2@51,12.3 51.025,12.3 51.35,12.625 v1(51.575,12.625) ; v1(67.425,12.575) LED2.1@68.075,12.575 ; v1(80.65,35.05) 80.894,35.294 80.894,35.744 v1(80.9,35.75) C1.1@81.65,35.75 ; C1.1@81.9,35.75 C2.1@82.95,35.75 ; C2.1@83.05,35.75 U1.3@84.15,35.75 ; v1(105.2,50.2) R150.2@105.95,50.2 ; R108.1@106.25,49.5 105.95,49.8 R150.2@105.95,50.2 ; R109.1@106.25,50.95 105.95,50.65 R150.2@105.95,50.2
  Top Layer w0.635: SW704.5@20.9,1.75 v1(20.9,3.575) v1(20.9,4.325) ; v1(100.2,17.45) v1(100.875,17.45) v1(101.55,17.45) 102.475,17.45 103.595,18.57 P101.2@104.57,18.57 ; P801.1@101.715,57.841 101.715,57.085 102.6,56.2 v1@102.6,51.35
  Signal Layer 3 w0.6: v1(19.577,24.551) 20.999,24.551 21.75,23.8 v1(23.4,23.8) 24.825,22.375 v1(30.1,22.375) v1(30.9,22.375)
  Signal Layer 4 w0.3: v1(19.577,24.551) v1@19.625,24.503
  Signal Layer 4 w0.5: v1(38.95,22.375) 38.95,27 40.725,28.775 v1(40.725,30.375)
  Bottom Layer w0.3: v1(80.9,35.75) 80.9,35.8 TP157.1@81.6,36.5
  Bottom Layer w0.635: TP703.1@28.9,4.7 29.512,4.7 J101.1@30.95,3.262
  other v1: 102.6,51.325
VMCU_BUF: C625.1 C861.1 C863.1 C865.1 C867.1 R630.2 R675.2 U806.2 U860.6 U861.6 U862.6 U863.6 | length 110
  Top Layer w0.2: U860.6@51.6,47.65 51.65,47.65 52.175,47.125 C863.1@52.175,47.05 52.175,46.525 v1(52.15,46.5) ; C861.1@61.45,38.55 U862.6@62.1,38.55 ; v1(66.175,34.1) 66.225,34.15 C867.1@66.725,34.15 U863.6@67.35,34.15 ; C865.1@66.65,40.275 67.225,40.275 U861.6@67.25,40.25
  Top Layer w0.3: R630.2@52.15,32.2 v1(52.625,32.2) ; v1(61.45,38) C861.1@61.45,38.55 ; v1(66.075,40.65) 66.425,40.3 66.65,40.3 C865.1@66.65,40.275 ; U806.2@71.9,35.8 71.9,35.95 72.075,36.125 72.65,36.125 73.125,36.6 v1(73.275,36.6)
  Top Layer w0.5: C625.1@33.3,27.475 R675.2@33.3,26.425 v1(34,26.425)
  Signal Layer 3 w0.5: v1(34,26.425) 35.975,24.45 58.05,24.45 v1(58.575,24.975) v1(59.113,25.512) ; v1(58.265,38.85) 60.6,38.85 v1(61.45,38)
  Signal Layer 4 w0.35: 55.275,45.85 55.3,45.825 55.825,45.825
  Signal Layer 4 w0.4: v1(52.15,46.5) 52.15,46.4 52.525,46.025 53.475,46.025 53.85,45.65 54.825,45.65 55.025,45.85 55.275,45.85
  Signal Layer 4 w0.5: 55.825,45.825 56.575,45.075 56.575,41.7 58.265,40.01 v1(58.265,38.85)
  Bottom Layer w0.3: v1(52.625,32.2) 53,31.825 55.225,31.825 ; v1(72.975,28.3) 72.975,29.7 72.1,30.575 72.1,31.075 72.625,31.6 72.625,34.25 73.275,34.9 v1(73.275,36.6)
  Bottom Layer w0.5: 55.225,31.825 56.6,30.45 59.65,30.45 ; v1(58.575,24.975) v1(59.113,25.512) 59.65,26.05 59.65,27.45 ; v1(61.45,38) v1@61.388,38.063 ; v1(66.075,40.65) 63.6,40.65 62.75,39.8 62.75,39.425 v1@61.388,38.063 ; v1(66.175,34.1) 62.35,34.1 60.875,32.625 59.65,32.625 ; v1(72.975,28.3) 72,27.325 69.8,27.325 69.125,26.65 66.05,26.65 65.25,27.45 59.65,27.45 ; 59.65,27.45 59.65,30.45 ; 59.65,30.45 59.65,32.625 ; 59.65,32.625 59.65,36.325 v1@61.388,38.063
VMCU_R: C761.1 C762.1 Q705.1 R701.1 R702.2 R709.2 TP700.1 U701.1 U701.4 | length 27.7
  Top Layer w0.1: R709.2@30.35,36.2 29.825,35.675 29.825,35 30.125,34.7 R701.1@31.175,34.7
  Top Layer w0.25: v1(29.825,32.7) 29.875,32.65 U701.4@30.35,32.65 ; U701.1@31.85,32.65 v1@32.325,32.65
  Top Layer w0.3: v1(30.075,28.325) 30.325,28.575 R702.2@30.325,28.85
  Top Layer w0.5: C762.1@28.2,33.225 29.025,33.225 C761.1@29.1,33.15 ; R701.1@31.175,34.7 31.175,34.425 30.66,33.91 30.485,33.91 v1(29.85,33.275) ; C761.1@29.1,33.15 29.225,33.275 29.538,33.275 ; C761.1@29.1,33.15 29.538,32.713 ; 29.538,32.713 29.538,33.275 ; 29.538,32.713 29.55,32.7 v1(29.825,32.7) 29.85,32.725 v1(29.85,33.275) ; 29.538,33.275 v1(29.85,33.275) ; v1@25.375,32.25 v1(25.375,32.4) 25.463,32.488 Q705.1@25.9,32.488 25.9,31.975 v1(25.775,31.85) v1@25.375,32.25
  Signal Layer 3 w0.6: v1(25.375,32.4) 25.7,32.4 25.775,32.325 ; v1(25.775,31.85) 25.775,32.325 ; v1(32.375,32.6) 32.35,32.575 29.95,32.575 v1(29.825,32.7) 29.825,33.25 v1(29.85,33.275) 26.725,33.275 25.775,32.325
  Signal Layer 4 w0.5: v1(29.85,33.275) 29.85,31.675 29.975,31.55 29.975,28.425 v1(30.075,28.325)
  Bottom Layer w0.5: v1(29.825,32.7) 29.825,34.325 TP700.1@29.9,34.4
VMCU_S: C700.1 C701.1 Q705.4 R701.2 R710.2 R760.2 TP701.1 TP705.1 U702.2 U702.4 U702.9 U702.10 | length 32.5
  Top Layer w0.1: R701.2@28.325,34.7 29.325,34.7 29.625,35 29.625,35.725 R710.2@29.15,36.2
  Top Layer w0.2: U702.10@41.815,36.675 42.5,36.675 v1(42.602,36.777) ; U702.9@41.815,37.075 42.25,37.075 v1@42.475,36.85 ; U702.2@43.585,36.275 43.2,36.275 42.698,36.777 v1(42.602,36.777) ; U702.4@43.585,37.075 43.175,37.075 43,36.9 42.725,36.9 v1(42.602,36.777)
  Top Layer w0.3: v1(25.025,35.475) 25.125,35.575 R760.2@25.55,35.575
  Top Layer w0.5: R760.2@25.55,35.575 26.575,35.575 C700.1@27,35.15 ; v1@27.556,35.844 v1(27.556,35.831) 27.556,35.706 C700.1@27,35.15 ; R701.2@28.325,34.7 27.938,34.313 Q705.4@27.2,34.313 27.2,34.95 C700.1@27,35.15
  Signal Layer 3 w0.6: v1(25.025,35.475) 25.381,35.831 v1(27.556,35.831) 28.131,35.831 28.9,36.6 42.425,36.6 v1(42.602,36.777)
  Bottom Layer w0.5: v1(27.556,35.831) 28.431,35.831 TP701.1@28.6,36 ; TP705.1@41.6,36.2 42.177,36.777 v1(42.602,36.777)
VMCU_SENSE: C632.1 R630.1 R631.2 TP708.1 U910.6 | length 4.9
  Top Layer w0.1: v1(49.575,34.1) 49.65,34.025 U910.6@50.625,34.025 50.65,34 51.05,34 C632.1@51.05,32.775 51.075,32.8 R631.2@51.6,32.8 R630.1@52.15,32.8
  Bottom Layer w0.1: TP708.1@48.8,34.8 49.5,34.1 v1(49.575,34.1)
VREF: C3.1 C4.1 R5.1 TP158.1 | length 3.8
  Top Layer w0.3: v1(80.2,35.7) C3.1@80.2,36.45 80.4,36.65 C4.1@81.25,36.65 82.1,36.65 R5.1@82.15,36.7
  Bottom Layer w0.3: TP158.1@79.2,35.7 v1(80.2,35.7)
VTARGET: R629.2 R691.1 U800.1 U806.1 | length 22.6
  Top Layer w0.2: R629.2@69.3,26.5 69.95,26.5 R691.1@70,26.45 v1(70.675,26.45)
  Top Layer w0.3: U806.1@72.35,34.85 72.45,34.85 72.575,34.975 v1(72.575,35.325) ; U800.1@72.35,43.85 72.35,44.375 v1(72.475,44.5)
  Signal Layer 4 w0.3: v1(70.675,26.45) 72.45,28.225 v1(72.45,29.025) 71.65,29.825 71.65,31.275 72.2,31.825 72.2,34.95 v1(72.575,35.325) 72.593,35.343 72.593,39.668 73.025,40.1 73.025,40.65 72.85,40.825 72.85,44.125 v1(72.475,44.5)
VTARGET_BUF: C655.1 C806.1 L801.1 R636.2 R687.2 R801.2 R809.2 U808.23 U808.24 | length 59.9
  Top Layer w0.2: v1(64.05,47.35) 64.175,47.225 C806.1@64.175,46.85
  Top Layer w0.3: R636.2@47.2,32.8 47.2,33.625 v1(47.35,33.775) ; L801.1@54.7,37.3 L801.1@54.709,37.309 ; R809.2@54.925,38.125 54.925,37.525 L801.1@54.709,37.309 ; v1(55.575,37.312) 55.572,37.309 L801.1@54.709,37.309 ; C806.1@64.15,46.825 U808.24@64.15,45.845 65.005,45.845 65.195,45.655 U808.23@65.195,45.3 ; R801.2@67.85,42.7 68.1,42.7 68.45,43.05 v1(68.525,43.05)
  Top Layer w0.4: v1@61.125,25.5 C655.1@61.8,25.5 R687.2@61.8,26.55
  Signal Layer 3 w0.4: v1(47.35,33.775) 47.35,34.15 47.85,34.65 51.775,34.65 52.7,33.725 ; v1(55.575,37.312) 55.575,36.6 52.7,33.725 ; v1(61.075,25.5) 61.075,27.825 58.9,30 54.15,30 53.425,30.725 53.425,33 52.7,33.725
  Bottom Layer w0.3: v1(68.525,43.05) 68.85,43.375 68.85,43.954 68.625,44.179
  Bottom Layer w0.4: v1(55.575,37.312) 59.637,37.312 60.775,38.45 60.775,40.15 61.9,41.275 61.9,45.2 v1(64.05,47.35) 64.65,47.95 66.1,47.95 66.5,48.35 67.75,48.35 68.625,47.475 68.625,44.179
VTARGET_SENSE: C638.1 R636.1 R637.2 U910.5 | length 3.2
  Top Layer w0.1: C638.1@46.1,32.775 46.125,32.8 R637.2@46.65,32.8 ; U910.5@46.225,34.025 U910.5@46.65,34.025 ; U910.5@46.775,34.025 U910.5@46.65,34.025 ; R636.1@47.2,32.2 47.2,32.25 R637.2@46.65,32.8 ; R637.2@46.65,32.8 U910.5@46.65,34.025
VTREF: Q800.4 R816.2 TPJ817.1 U800.2 | length 51.3
  Top Layer w0.3: Q800.4@67.325,36.65 67.325,35.725 v1(67.45,35.6) ; U800.2@71.9,44.8 71.9,45.65 R816.2@71.95,45.7 72.025,45.775 v1(72.025,46.55)
  Signal Layer 3 w0.3: v1(67.2,46) 67.325,46.125 68.45,46.125 69.725,44.85 70.325,44.85 v1(72.025,46.55) 100.85,46.55 v1(101.875,47.575)
  Signal Layer 4 w0.3: v1(67.2,46) 66.65,45.45 66.65,39.425 67.175,38.9 67.175,37.825 67.45,37.55 v1(67.45,35.6)
  Bottom Layer w0.5: v1(101.875,47.575) TPJ817.1@102.65,48.35
pads on no net: D800.5 D801.1 D903.2 D903.4 D903.5 J101.5 J101.6 J101.7 J101.8 J101.9 J101.10 J101.11 J101.12 J102.5 J102.6 J102.7 J102.9 J102.11 J102.13 J102.14 J102.16 M2.1 M3.1 P100.11 P100.12 P101.M1 P101.M2 P601.25@1.8,56.82 P601.26@1.8,48.18 P601.27@6.25,56.525 P601.27@6.85,56.82 P601.28@6.25,48.475 P601.28@6.85,48.18 P601.A2 P601.A3 P601.A8 P601.A10 P601.A11 P601.B2 P601.B3 P601.B8 P601.B10 P601.B11 P601.M1 P601.M2 P800.7 P800.11 P800.13 P801.10 P801.12 P801.14 P801.16 P801.18 P801.20 P801.M1 P801.M2 Q100.3 RP800.2 RP800.7 SW105.7 SW105.8 SW105.M1 SW105.M2 U1.2 U102.3 U102.4 U102.7 U600.8 U701.8 U800.17 U802.17 U806.17 U808.8 U808.9 U808.10 U810.17 U900.B11 U900.G2 U900.H2 U900.J2 U900.L3 U900.L8 U900.L12 U900.M4 U900.M12 U900.N7 U900.N12 U901.9 U902.C1

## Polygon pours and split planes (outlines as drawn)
3V3 on VCC Layer 5 "3V3_L05_P004" (solid, remove dead copper, pour order 4): 44.511,36.2 44.511,40.7 42.9,40.7 42.9,43.6 28.35,43.6 25.65,46.3 18.325,46.3 12.825,51.8 12.825,60 33,60 100.575,60 100.575,43 102.4,43 102.4,40.375 68.925,40.375 68.925,24 29.3,24 29.3,6.775 20.075,6.775 20.075,0 0,0 0,36.2
VMCU on VCC Layer 5 "VMCU_L05_P005" (solid, remove dead copper, pour order 5): 20.375,0 20.375,6.425 29.725,6.425 29.725,23.5 69.3,23.5 69.3,40 102.725,40 102.725,43.325 101.075,43.325 101.075,60 115,60 115,0
GND on VCC Layer 5 "GND_L05_P003" (solid, remove dead copper, pour order 3): 44.25,36.5 44.25,40.5 42.65,40.5 42.65,43.3 28.35,43.3 25.65,46 18.275,46 12.6,51.675 12.6,55.6 12.6,60 0,60 0,46.25 0,36.5
GND on Top Layer "GND_L01_P002" (solid, remove dead copper, pour order 2): 0,0 0,60 125,60 125,0
GND on Bottom Layer "GND_L06_P008" (solid, remove dead copper, pour order 8): 0,0 0,60 125,60 125,0
GND on GND Layer 2 "GND_L02_P009" (solid, remove dead copper, pour order 9): 0,0 0,60 125,60 125,0
GND on Signal Layer 3 "GND_L03_P011" (solid, remove dead copper, pour order 11): 0,0 0,60 125,60 125,0
GND on Signal Layer 4 "GND_L04_P012" (solid, remove dead copper, pour order 12): 0,0 0,60 125,60 125,0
